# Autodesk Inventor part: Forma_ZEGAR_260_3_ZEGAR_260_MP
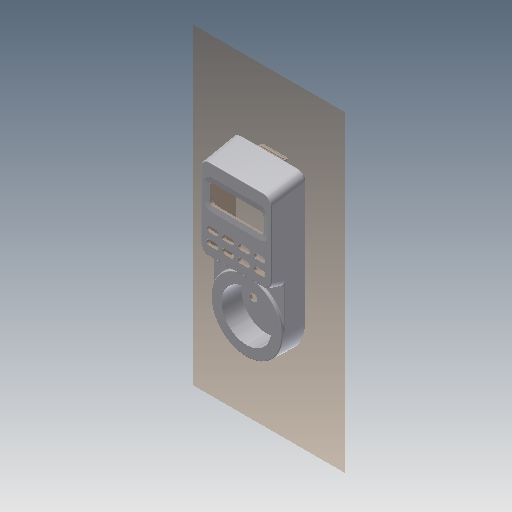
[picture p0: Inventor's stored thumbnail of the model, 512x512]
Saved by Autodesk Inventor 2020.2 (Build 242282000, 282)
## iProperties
Created: 2015-01
Part Number: Forma_ZEGAR_260_3_ZEGAR_260_MP
Material: Ogólny
Document SubType Name: Modeling
Designer: F.Stasiak
Density: 1 g/cm^3
Appearance: Domyślna
Catalog Web Link: www.expertbooks.pl
Manager: www.cadconsulting.pl
Company: Fabian Stasiak CAD Consulting
Author: F.Stasiak
Subject: Zbiór ćwiczeń. Autodesk Inventor 2020. Kurs Professional
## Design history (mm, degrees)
derived "ZEGAR_260.ipt"
node "Forma_ZEGAR_260_3_ZEGAR_260_WP"
feature "Zamknij obwiednię1" dims "d7" = 5, "d8" = 5, "d9" = 5, "d10" = 5, "d11" = 0
feature "Zamknij obwiednię2" dims "d12" = 5, "d13" = 5, "d14" = 5, "d15" = 5, "d16" = 0
feature "Zamknij obwiednię3" dims "d17" = 5, "d18" = 5, "d19" = 5, "d20" = 5, "d21" = 5, "d22" = 5, "d23" = 5, "d24" = 5, "d25" = 0
feature "Zamknij obwiednię4" dims "d26" = 5, "d27" = 5, "d28" = 5, "d29" = 5, "d30" = 0
feature "Zamknij obwiednię5" dims "d31" = 5, "d32" = 5, "d33" = 5, "d34" = 5, "d35" = 0
feature "Zamknij obwiednię6" dims "d36" = 5, "d37" = 5, "d38" = 5, "d39" = 5, "d40" = 0
feature "Zamknij obwiednię7" dims "d41" = 5, "d42" = 5, "d43" = 5, "d44" = 5, "d45" = 0
feature "Zamknij obwiednię8" dims "d46" = 5, "d47" = 5, "d48" = 5, "d49" = 5, "d50" = 0
feature "Zamknij obwiednię9" dims "d51" = 5, "d52" = 5, "d53" = 5, "d54" = 5, "d55" = 0
feature "Zamknij obwiednię10" dims "d56" = 5, "d57" = 0
feature "Zamknij obwiednię11" dims "d58" = 5, "d59" = 0
feature "Zamknij obwiednię12" dims "d60" = 5, "d61" = 0
node "Płaszczyzna konstrukcyjna1"
sketch "Szkic1"
  geometry: L1 (30.835, -178.031)-(30.835, 61.969); L2 (30.835, 61.969)-(-86.165, 61.969); L3 (-86.165, 61.969)-(-86.165, -178.031); L4 (-86.165, -178.031)-(30.835, -178.031); L5 (0, 0)-(0, -94.499) reference; L6 (-55.33, -94.499)-(-55.33, 0) reference; L7 (-49.319, 6.101)-(-6.011, 6.101) reference; A1 r 27.665 centre (-27.665, -94.499) between (-55.33, -94.499) and (0, -94.499) reference; 3 further points; 2 other entities
  constraints: 8 end point, 2 other
  dimensions: "d62" = 58.5 horizontal distance of point (-27.665, -58.031) L1.end (= 1.5 x Xmax); "d63" = 120 vertical distance of point (-27.665, -58.031) L1.end (= 1.5 x Ymax); "d64" = 58.5 horizontal distance of point (-27.665, -58.031) L2.end (= -1.5 x Xmin); "d65" = 120 vertical distance of point (-27.665, -58.031) L2.end (= 1.5 x Ymax); "d66" = 58.5 horizontal distance of point (-27.665, -58.031) L3.end (= -1.5 x Xmin); "d67" = 120 vertical distance of point (-27.665, -58.031) L3.end (= -1.5 x Ymin); "d68" = 58.5 horizontal distance of point (-27.665, -58.031) L1.start (= 1.5 x Xmax); "d69" = 120 vertical distance of point (-27.665, -58.031) L1.start (= -1.5 x Ymin)
feature "Zamknij obwiednię13" sketch "Szkic1"
feature "Oddzielenie matrycy1"
node "Płaszczyzna konstrukcyjna2"
sketch "Szkic2"
  geometry: L1 (0, -78)-(-20.191, -78) reference; L2 (-20.191, -78)-(-20.191, 0) reference; L3 (-17.791, -39)-(-12.991, -39); L4 (-17.791, -39)-(-15.391, -39); L5 (-17.791, -39)-(-17.791, -29.75); L6 (-20.191, -48.25)-(-15.391, -48.25); L7 (-15.391, -48.25)-(-15.391, -29.75); L8 (-15.391, -29.75)-(-20.191, -29.75); L9 (-20.191, -29.75)-(-20.191, -48.25)
  constraints: 14 end point, 1 horizontal, 1 perpendicular, 2 other
  dimensions: "d71" = 39 distance from line of L1 L3.start; "d72" = 2.4 distance from line of L2 L3.start; "d73" = 0 distance between parallel lines of L3 L4; "d74" = 4.8 distance between parallel lines of L9 L7; "d75" = 18.5 distance between parallel lines of L8 L6
extrude "Wyciągnięcie proste1" new body sketch "Szkic2" stored distance "d76" = 0.13; taper "d77" = 0 deg
node "Płaszczyzna konstrukcyjna3"
sketch "Szkic3"
  geometry: L1 (0, -18.5)-(-4.8, -18.5) reference; L2 (-4.8, -18.5)-(-4.8, 0) reference; L3 (-1.8, -9.25)-(4.2, -9.25); L4 (-1.8, -9.25)-(1.2, -9.25); L5 (-1.8, -9.25)-(-1.8, 5.75); L6 (-4.8, -24.25)-(1.2, -24.25); L7 (1.2, -24.25)-(1.2, 5.75); L8 (1.2, 5.75)-(-4.8, 5.75); L9 (-4.8, 5.75)-(-4.8, -24.25)
  constraints: 14 end point, 1 horizontal, 1 perpendicular, 2 other
  dimensions: "d79" = 9.25 distance from line of L1 L3.start; "d80" = 3 distance from line of L2 L3.start; "d81" = 0 distance between parallel lines of L3 L4; "d82" = 6 distance between parallel lines of L9 L7; "d83" = 30 distance between parallel lines of L8 L6
extrude "Wyciągnięcie proste2" join sketch "Szkic3" distance "d84" = 8; taper "d85" = 0 deg
feature "Bryła1::ZEGAR_260.ipt"
tag "Bryła wyprowadzona1"
feature "Bryła1::Forma_ZEGAR_260_3_ZEGAR_260_WP"
tag "Bryła wyprowadzona2"
body "Srf1"
body "Srf2"
body "Srf3"
body "Srf4"
body "Srf5"
body "Srf6"
body "Srf7"
body "Srf8"
body "Srf9"
body "Srf10"
body "Srf11"
body "Srf12"
body "Srf13"
node "Bryła3"
node "Bryła4"
node "Bryła5"
node "Bryła1"
feature "ZEGAR_260.ipt_Bodies"
node "Bryła2"
feature "Forma_ZEGAR_260_3_ZEGAR_260_WP_Bodies"
other parameters: "d1" = 39, "d2" = 39, "d6" = 0, "Xmin" = -39, "Xmax" = 39, "d70" = 0, "d78" = 0
